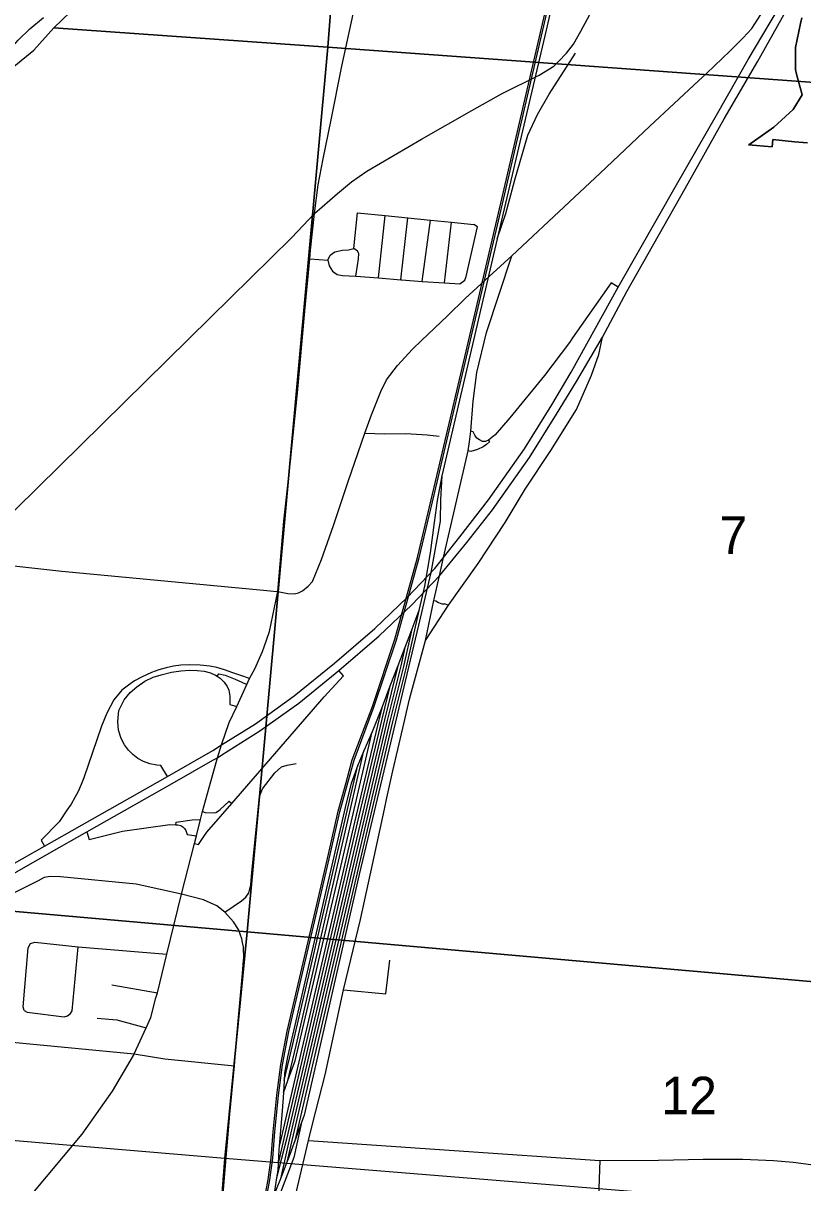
# Model space of a CAD drawing. Extents: x 0 to 34, y 0 to 22.
# Drawn here: x 4.57 to 5.442, y 14.854 to 16.149 of the extents above; entities that cross this region are included whole.
import ezdxf

# ---------------------------------------------------------------- set-up
doc = ezdxf.new("R2010")
doc.units = 0
for name, color, linetype in [('Default', 7, 'Continuous'), ('GM_X_City_Street', 7, 'Continuous'), ('GM_X_Interchange_Ramps', 7, 'Continuous'), ('GM_X_Interstate_Route', 7, 'Continuous'), ('GM_X_Major_River', 7, 'Continuous'), ('GM_X_Rail_Line', 7, 'Continuous'), ('GM_X_Section', 7, 'Continuous'), ('GM_X_Section_Text', 7, 'Continuous'), ('GM_X_State_Route', 7, 'Continuous'), ('SC_Shading3', 7, 'Continuous')]:
    doc.layers.add(name, color=color, linetype=linetype)

msp = doc.modelspace()

# ---------------------------------------------------------------- linework, layer by layer
at = {"layer": 'Default'}
for points in [[(3.9705, 14.1), (4.7349, 14.1), (4.7957, 14.8813), (4.1906, 14.9321), (4.0525, 14.6548), (3.9958, 14.4577), (3.9463, 14.3814), (3.9481, 14.3196)], [(4.7349, 14.1), (5.7681, 14.1), (5.8197, 14.7981), (4.7957, 14.8813)]]:
    msp.add_lwpolyline(points, close=True, dxfattribs=at)
at = {"layer": 'GM_X_City_Street'}
for p, q in [((4.9673, 15.8644), (4.975, 15.9342)), ((4.9923, 15.8625), (5.0002, 15.9317)), ((5.0161, 15.8606), (5.0253, 15.9291)), ((5.0411, 15.8591), (5.0491, 15.9267)), ((4.8906, 15.8858), (4.9107, 15.8843)), ((4.9754, 15.0651), (4.98, 15.1028)), ((4.6695, 15.075), (4.7203, 15.0661)), ((4.9281, 15.0695), (4.9754, 15.0651))]:
    msp.add_line(p, q, dxfattribs=at)
for points in [[(4.8397, 15.4527), (4.8456, 15.4697), (4.855, 15.5142), (4.8617, 15.5929), (4.869, 15.6599), (4.8767, 15.7363), (4.8851, 15.8274), (4.8906, 15.8858), (4.8915, 15.8956), (4.8959, 15.9365), (4.9, 15.9686), (4.9055, 15.9974), (4.9143, 16.0411), (4.9265, 16.101), (4.9418, 16.1711), (4.9536, 16.2272), (4.9641, 16.2778), (4.9703, 16.3128)], [(4.5149, 15.5535), (4.5216, 15.5642), (4.5305, 15.5745), (4.5624, 15.6068), (4.7794, 15.82), (4.87, 15.9094), (4.8959, 15.9365), (4.9216, 15.9589), (4.9372, 15.9717), (4.9543, 15.9837), (5.0154, 16.0193), (5.0715, 16.0516), (5.1047, 16.0699), (5.1468, 16.091), (5.1632, 16.1008), (5.1685, 16.1061), (5.1775, 16.1154), (5.1852, 16.1256), (5.1933, 16.1399), (5.2233, 16.1956), (5.23, 16.2068), (5.2368, 16.2142), (5.2425, 16.2183)], [(5.3343, 16.0932), (5.3599, 16.1177), (5.375, 16.1324), (5.3844, 16.1431), (5.3947, 16.1587), (5.4033, 16.173), (5.4082, 16.1836), (5.4117, 16.1912), (5.4129, 16.2047), (5.4122, 16.2135)], [(4.85, 15.5147), (4.855, 15.5142), (4.866, 15.5122), (4.8731, 15.5116), (4.8778, 15.5129), (4.8824, 15.5149), (4.8888, 15.5202), (4.8937, 15.5254), (4.9038, 15.5501), (4.917, 15.5879), (4.9336, 15.6372), (4.952, 15.6912), (4.9595, 15.7116), (4.9699, 15.7376), (4.9765, 15.7506), (4.9885, 15.7667), (5.0054, 15.785), (5.0153, 15.7946), (5.0444, 15.822), (5.0642, 15.8414), (5.0911, 15.866), (5.1163, 15.8891), (5.1809, 15.9495), (5.215, 15.9815), (5.2705, 16.0338), (5.3248, 16.0844), (5.3343, 16.0932)], [(4.9107, 15.8843), (4.9134, 15.8898), (4.9187, 15.8936), (4.9271, 15.8954), (4.9338, 15.8958), (4.9399, 15.8972), (4.9439, 15.9371)], [(4.9439, 15.9371), (4.975, 15.9342), (5.0002, 15.9317), (5.0253, 15.9291), (5.0491, 15.9267), (5.0739, 15.9242)], [(5.0582, 15.8579), (5.0637, 15.862), (5.0652, 15.8659), (5.0781, 15.9215), (5.0739, 15.9242)], [(4.9421, 15.8664), (4.9439, 15.8782), (4.9451, 15.8859), (4.9453, 15.8916), (4.9438, 15.8943), (4.9399, 15.8972)], [(5.0198, 15.4595), (5.0291, 15.5043), (5.0354, 15.5319), (5.0401, 15.5522), (5.0675, 15.6715), (5.0691, 15.6815), (5.0705, 15.6934), (5.0733, 15.7267), (5.0771, 15.759), (5.0879, 15.8035), (5.1163, 15.8891)], [(4.9107, 15.8843), (4.9123, 15.8779), (4.9161, 15.872), (4.9212, 15.8683), (4.9273, 15.8672), (4.9421, 15.8664), (4.9673, 15.8644), (4.9923, 15.8625), (4.9936, 15.8623), (5.0161, 15.8606), (5.0411, 15.8591), (5.0582, 15.8579)], [(4.952, 15.6912), (4.9745, 15.6905), (4.998, 15.6907), (5.0218, 15.6891), (5.0352, 15.6879)], [(4.5149, 15.5535), (4.525, 15.5488), (4.5328, 15.5458), (4.6135, 15.5372), (4.839, 15.5157), (4.85, 15.5147)], [(4.8234, 15.4172), (4.8293, 15.4281), (4.8379, 15.4473), (4.8397, 15.4527)], [(4.7684, 15.2597), (4.7707, 15.2685), (4.7801, 15.3021), (4.7873, 15.3287), (4.7921, 15.343), (4.8006, 15.3679), (4.809, 15.3859), (4.8202, 15.4103), (4.8234, 15.4172)], [(4.7958, 15.1563), (4.8142, 15.1689), (4.819, 15.1729), (4.8224, 15.1777), (4.8246, 15.1867), (4.8259, 15.2005), (4.8344, 15.2853), (4.8378, 15.2941), (4.8515, 15.3118), (4.8589, 15.3185), (4.8654, 15.3205), (4.8752, 15.3224)], [(4.7473, 15.1764), (4.7616, 15.2328), (4.7639, 15.2414), (4.7684, 15.2597)], [(4.7473, 15.1764), (4.6964, 15.1876), (4.612, 15.1957), (4.6004, 15.1961), (4.5936, 15.195), (4.5869, 15.1914), (4.5085, 15.1522), (4.4981, 15.1441), (4.4919, 15.1361), (4.4886, 15.1229), (4.4801, 15.0184)], [(4.7187, 15.0604), (4.7203, 15.0661), (4.7309, 15.1092), (4.7473, 15.1764)], [(4.7958, 15.1563), (4.7866, 15.1632), (4.7718, 15.17), (4.7473, 15.1764)], [(4.8155, 15.1224), (4.8147, 15.1264), (4.8108, 15.1369), (4.8055, 15.1456), (4.7958, 15.1563)], [(4.5714, 15.0466), (4.5704, 15.0506), (4.5759, 15.1163), (4.5786, 15.1211)], [(4.5786, 15.1211), (4.5835, 15.1228), (4.6317, 15.1176), (4.7309, 15.1092)], [(4.6233, 15.0432), (4.6249, 15.0462), (4.6317, 15.1176)], [(4.8165, 15.1025), (4.8167, 15.1045), (4.8165, 15.1175), (4.8155, 15.1224)], [(4.7877, 14.7751), (4.7915, 14.8137), (4.795, 14.8556), (4.8014, 14.9307), (4.8064, 14.9848), (4.8088, 15.0142), (4.8154, 15.0879), (4.8165, 15.1025)], [(4.6934, 14.9962), (4.6944, 14.9979), (4.7077, 15.0271), (4.7129, 15.0385), (4.7187, 15.0604)], [(4.5714, 15.0466), (4.5748, 15.0447), (4.6162, 15.0395), (4.6198, 15.0403), (4.6233, 15.0432)], [(4.653, 15.0379), (4.6749, 15.036), (4.7077, 15.0271)], [(4.3785, 15.0286), (4.4007, 15.026), (4.4801, 15.0184), (4.6944, 14.9979), (4.7286, 14.9924), (4.8064, 14.9848)], [(4.5036, 14.7192), (4.5157, 14.7466), (4.542, 14.7907), (4.5756, 14.8358), (4.6361, 14.9083), (4.67, 14.9564), (4.6934, 14.9962)], [(4.889, 14.9013), (5.2146, 14.8789), (5.2803, 14.8794), (5.3302, 14.8805), (5.3744, 14.8805), (5.4089, 14.8788), (5.4308, 14.8769), (5.4841, 14.8699), (5.5184, 14.8616), (5.5803, 14.8433), (5.6231, 14.829), (5.6609, 14.8201), (5.6846, 14.8159)], [(5.2146, 14.8789), (5.2126, 14.8172), (5.2077, 14.7541), (5.1981, 14.658), (5.1943, 14.628), (5.1877, 14.5576), (5.1889, 14.5431), (5.1938, 14.5246), (5.1999, 14.5119), (5.2062, 14.5004), (5.2164, 14.4886), (5.226, 14.4817), (5.2454, 14.4704), (5.345, 14.4199), (5.4323, 14.3694), (5.5063, 14.3244), (5.5711, 14.2911)]]:
    msp.add_lwpolyline(points, dxfattribs=at)
at = {"layer": 'GM_X_Interchange_Ramps'}
for points in [[(5.2353, 15.8542), (5.2273, 15.8589), (5.1843, 15.7976)], [(5.1843, 15.7976), (5.1807, 15.7925), (5.1529, 15.7555), (5.114, 15.7082), (5.0978, 15.6892), (5.0904, 15.6832)], [(5.0904, 15.6832), (5.0916, 15.6813), (5.0879, 15.6785), (5.0844, 15.676), (5.078, 15.673), (5.0706, 15.6708), (5.0675, 15.6715)], [(5.0904, 15.6832), (5.087, 15.6818), (5.0837, 15.682), (5.0802, 15.6835), (5.0773, 15.6854), (5.0749, 15.6889), (5.0732, 15.6927), (5.0705, 15.6934)], [(5.0291, 15.5043), (5.0313, 15.504), (5.0345, 15.5019), (5.0382, 15.5005), (5.0418, 15.5007), (5.0457, 15.4989)], [(4.8234, 15.4172), (4.8148, 15.42), (4.8045, 15.4235), (4.7952, 15.4269), (4.7866, 15.4293), (4.779, 15.4309), (4.7682, 15.4322), (4.7567, 15.4326), (4.7466, 15.432), (4.7384, 15.4309), (4.73, 15.4292), (4.722, 15.427), (4.7138, 15.424), (4.7025, 15.4188), (4.6948, 15.4144), (4.6881, 15.4099), (4.6807, 15.4041), (4.6716, 15.3935), (4.6637, 15.3784), (4.6578, 15.3639), (4.6381, 15.3064), (4.6352, 15.2989), (4.6317, 15.2911), (4.6282, 15.2844), (4.6238, 15.277), (4.6191, 15.27), (4.6104, 15.2572), (4.5905, 15.2365), (4.5943, 15.2301)], [(4.7317, 15.3079), (4.7243, 15.3201), (4.7197, 15.3202), (4.7119, 15.3218), (4.7048, 15.3245), (4.6984, 15.328), (4.6927, 15.3324), (4.6879, 15.3373), (4.6836, 15.3431), (4.6799, 15.3502), (4.677, 15.3594), (4.6759, 15.369), (4.6773, 15.3815), (4.6831, 15.3932), (4.69, 15.4017), (4.6972, 15.408), (4.7064, 15.414), (4.7157, 15.4186), (4.7244, 15.4214), (4.7361, 15.4242), (4.7463, 15.4258), (4.7565, 15.4266), (4.7646, 15.4262), (4.7725, 15.4253), (4.7797, 15.4234), (4.7854, 15.4209), (4.7871, 15.4198), (4.7905, 15.4176), (4.795, 15.4131), (4.7984, 15.4082), (4.8, 15.4042), (4.8012, 15.3976), (4.8013, 15.388), (4.809, 15.3859)], [(4.7616, 15.2328), (4.7664, 15.2317), (4.7722, 15.2408), (4.7755, 15.2454), (4.8033, 15.2775), (4.9067, 15.3968), (4.9284, 15.4202), (4.9231, 15.4262)], [(4.7871, 15.4198), (4.7891, 15.4225), (4.7961, 15.4207), (4.8073, 15.4166), (4.8148, 15.4131), (4.8202, 15.4103)], [(4.7707, 15.2685), (4.7738, 15.2676), (4.7829, 15.267), (4.7855, 15.2674), (4.7885, 15.2693), (4.7903, 15.271), (4.8004, 15.28), (4.8033, 15.2775)], [(4.6413, 15.2458), (4.6442, 15.2373), (4.6813, 15.2467), (4.7342, 15.2542), (4.7409, 15.2538), (4.743, 15.2536), (4.7464, 15.2529), (4.7486, 15.2514), (4.7505, 15.2497), (4.752, 15.2474), (4.7537, 15.243), (4.7639, 15.2414)], [(4.7409, 15.2538), (4.7411, 15.2566), (4.7591, 15.2593), (4.7684, 15.2597)]]:
    msp.add_lwpolyline(points, dxfattribs=at)
at = {"layer": 'GM_X_Interstate_Route'}
for points in [[(4.7921, 15.343), (4.8298, 15.3667), (4.8732, 15.3979), (4.9182, 15.4343), (4.9631, 15.4729), (4.9995, 15.5075), (5.0305, 15.54), (5.0401, 15.5522), (5.0584, 15.5755), (5.0902, 15.6165), (5.1305, 15.6735), (5.1609, 15.7227), (5.1825, 15.7591), (5.2353, 15.8542), (5.3003, 15.9684), (5.345, 16.0461), (5.3805, 16.1084), (5.4224, 16.1794), (5.4322, 16.1982)], [(5.2177, 15.7982), (5.245, 15.8495), (5.3099, 15.9645), (5.3538, 16.0423), (5.3911, 16.1066), (5.4309, 16.1772), (5.4366, 16.1874)], [(4.7922, 15.3318), (4.8348, 15.3586), (4.8782, 15.3898), (4.9231, 15.4262), (4.9681, 15.4648), (5.0045, 15.4994), (5.0354, 15.5319), (5.0661, 15.569), (5.0949, 15.6056), (5.1363, 15.6639), (5.1664, 15.7122), (5.1887, 15.749), (5.2177, 15.7982)], [(4.3958, 15.0979), (4.3965, 15.0986), (4.411, 15.1122), (4.4246, 15.1249), (4.4406, 15.1364), (4.4557, 15.1489), (4.4695, 15.1575), (4.4939, 15.1734), (4.5199, 15.1877), (4.544, 15.2017), (4.5943, 15.2301), (4.6364, 15.2539), (4.7317, 15.3079), (4.7824, 15.3368), (4.7921, 15.343)], [(4.3383, 15.0004), (4.3568, 15.0308), (4.3814, 15.0645), (4.4051, 15.0915), (4.4356, 15.12), (4.4626, 15.1408), (4.4941, 15.1619), (4.5273, 15.181), (4.5992, 15.222), (4.6413, 15.2458), (4.7367, 15.2999), (4.7823, 15.3258)], [(4.7823, 15.3258), (4.7873, 15.3287), (4.7922, 15.3318)]]:
    msp.add_lwpolyline(points, dxfattribs=at)
at = {"layer": 'GM_X_Major_River'}
msp.add_lwpolyline([(4.3831, 15.9009), (4.389, 15.9129), (4.3945, 15.9231), (4.4001, 15.9359), (4.4049, 15.9506), (4.4145, 15.974), (4.42, 15.9838), (4.4286, 15.9981), (4.4387, 16.0097), (4.4503, 16.0231), (4.4612, 16.0351), (4.4739, 16.047), (4.4843, 16.0548), (4.4966, 16.0633), (4.5063, 16.0699), (4.5171, 16.0811), (4.5302, 16.093), (4.5434, 16.1069), (4.5542, 16.1181), (4.5647, 16.13), (4.5779, 16.1427), (4.5929, 16.1553)], dxfattribs=at)
at = {"layer": 'GM_X_Rail_Line'}
for p, q in [((5.0124, 15.4931), (5.0046, 15.4724)), ((4.989, 15.4314), (4.9802, 15.4085)), ((4.9802, 15.4085), (4.9713, 15.3856)), ((4.9713, 15.3856), (4.9604, 15.3576)), ((4.9604, 15.3576), (4.9511, 15.3364)), ((4.862, 14.9682), (4.8611, 14.9545)), ((4.8611, 14.9545), (4.866, 14.9681)), ((4.8649, 14.8771), (4.8577, 14.8584)), ((4.8535, 14.8594), (4.8501, 14.8374))]:
    msp.add_line(p, q, dxfattribs=at)
for points in [[(4.839, 14.8294), (4.8441, 14.8577), (4.8473, 14.8818), (4.8498, 14.9111), (4.8536, 14.9518), (4.8581, 14.9862), (4.8654, 15.0235), (4.901, 15.1758), (4.9115, 15.221), (4.9223, 15.2689), (4.9311, 15.301), (4.9381, 15.3264), (4.9605, 15.3858), (4.9858, 15.4611), (5.0111, 15.5524), (5.0295, 15.6307), (5.0403, 15.6765), (5.0637, 15.7765), (5.104, 15.9478), (5.2062, 16.3872)], [(4.8409, 14.829), (4.846, 14.8574), (4.8492, 14.8816), (4.8517, 14.911), (4.8555, 14.9516), (4.86, 14.9859), (4.8673, 15.0231), (4.9029, 15.1754), (4.9134, 15.2206), (4.9242, 15.2684), (4.933, 15.3005), (4.94, 15.3258), (4.9623, 15.3852), (4.9876, 15.4605), (5.013, 15.5519), (5.0313, 15.6302), (5.0422, 15.6761), (5.0656, 15.7761), (5.1058, 15.9473), (5.2081, 16.3868)], [(5.1737, 16.2391), (5.1682, 16.2002), (5.1547, 16.1411), (5.1078, 15.9417), (5.038, 15.6433)], [(5.1, 15.9083), (5.1095, 15.9365), (5.1199, 15.9739), (5.1341, 16.0238), (5.1452, 16.0469), (5.1581, 16.0697), (5.1875, 16.1155)], [(5.038, 15.6433), (5.0367, 15.617), (5.0364, 15.5929), (5.026, 15.5354), (5.0141, 15.4844), (4.9459, 15.1982), (4.8842, 14.9294), (4.8737, 14.9007)], [(5.038, 15.6433), (5.0331, 15.616), (5.0295, 15.5914), (5.0252, 15.5575), (5.0186, 15.5204), (5.0124, 15.4931)], [(5.0124, 15.4931), (4.9982, 15.4299), (4.9831, 15.3688), (4.9558, 15.253), (4.8737, 14.9007)], [(5.0046, 15.4724), (4.9952, 15.4306), (4.9801, 15.3695), (4.9528, 15.2537), (4.8706, 14.9014), (4.8649, 14.8771)], [(5.0046, 15.4724), (5.0012, 15.4635), (4.9968, 15.4517)], [(4.9968, 15.4517), (4.9922, 15.4314), (4.9771, 15.3702), (4.9498, 15.2544), (4.8676, 14.9021), (4.8577, 14.8584)], [(4.9968, 15.4517), (4.992, 15.4391), (4.989, 15.4314)], [(4.989, 15.4314), (4.9741, 15.371), (4.9468, 15.2552), (4.8646, 14.9028), (4.8535, 14.8594)], [(4.9802, 15.4085), (4.971, 15.3717), (4.9437, 15.2559), (4.8615, 14.9035), (4.8552, 14.8756)], [(4.9713, 15.3856), (4.968, 15.3724), (4.9407, 15.2566), (4.8585, 14.9042), (4.8562, 14.895)], [(4.866, 14.9681), (4.869, 14.9765), (4.8743, 14.9903), (4.9368, 15.2563), (4.9604, 15.3576)], [(4.866, 14.9681), (4.8754, 15.0074), (4.9511, 15.3364)], [(4.9511, 15.3364), (4.946, 15.3247), (4.9443, 15.3202)], [(4.862, 14.9682), (4.8717, 15.0087), (4.9443, 15.3202)], [(4.9443, 15.3202), (4.9368, 15.3), (4.9312, 15.278), (4.8657, 14.9946), (4.8624, 14.9765), (4.862, 14.9682)], [(4.8611, 14.9545), (4.8598, 14.9344), (4.8562, 14.895)], [(4.8813, 14.9215), (4.8726, 14.8821), (4.8628, 14.8558), (4.85, 14.8226), (4.8414, 14.7911), (4.8378, 14.7723), (4.8371, 14.7555), (4.8437, 14.7289), (4.8542, 14.7079), (4.8667, 14.6901), (4.8832, 14.676), (4.9032, 14.6641), (4.9272, 14.6562), (4.9509, 14.6562), (4.968, 14.6567)], [(4.8562, 14.895), (4.8559, 14.8913), (4.8552, 14.8756)], [(4.8737, 14.9007), (4.867, 14.8825), (4.8649, 14.8771)], [(4.8552, 14.8756), (4.8549, 14.868), (4.8535, 14.8594)], [(4.8577, 14.8584), (4.853, 14.8464), (4.8501, 14.8374)]]:
    msp.add_lwpolyline(points, dxfattribs=at)
at = {"layer": 'GM_X_Section'}
for points in [[(4.6046, 16.1438), (4.7052, 16.2404), (4.8924, 16.385), (4.9329, 16.4073), (4.9109, 16.1221)], [(4.9329, 16.4073), (4.9747, 16.391), (5.0349, 16.3524), (5.1555, 16.2978), (5.2124, 16.265), (5.3126, 16.2343), (5.437, 16.2217), (5.569, 16.217), (5.709, 16.1875), (5.8473, 16.1527), (5.9234, 16.1293), (5.9113, 16.0496), (4.9109, 16.1221)], [(4.6046, 16.1438), (4.9109, 16.1221), (4.8205, 15.1342), (4.2945, 15.1804), (4.324, 15.239), (4.3447, 15.3749), (4.3532, 15.5236), (4.3623, 15.7454), (4.3778, 15.8443), (4.4109, 15.9156), (4.4783, 16.0344), (4.5821, 16.1188)], [(4.9109, 16.1221), (5.9113, 16.0496), (5.8133, 15.0467), (4.8205, 15.1342)], [(4.2945, 15.1804), (4.8205, 15.1342), (4.7957, 14.8813), (4.1906, 14.9321), (4.222, 15.0068), (4.26, 15.0762), (4.2906, 15.1529)], [(4.8205, 15.1342), (5.8133, 15.0467), (5.8372, 15.0451), (5.8197, 14.7981), (4.7957, 14.8813)]]:
    msp.add_lwpolyline(points, close=True, dxfattribs=at)
at = {"layer": 'GM_X_State_Route'}
msp.add_line((4.889, 14.9013), (4.894, 14.9209), dxfattribs=at)
for points in [[(5.4405, 16.1551), (5.4391, 16.1486), (5.4333, 16.1219), (5.4332, 16.0973), (5.4346, 16.0919), (5.4407, 16.0689), (5.4407, 16.0688), (5.4308, 16.0526), (5.4093, 16.033), (5.3811, 16.0131), (5.3809, 16.013), (5.4074, 16.0107), (5.4081, 16.0191), (5.4324, 16.0166), (5.4468, 16.0152)], [(5.0198, 15.4595), (5.0457, 15.4989), (5.0786, 15.5454), (5.1089, 15.5914), (5.1313, 15.6287), (5.1601, 15.6716), (5.1887, 15.7176), (5.2054, 15.7559), (5.2135, 15.7791), (5.2177, 15.7982)], [(4.9767, 15.284), (4.9833, 15.314), (4.9944, 15.3618), (5.0021, 15.3942), (5.0198, 15.4595)], [(4.894, 14.9209), (4.9077, 14.9747), (4.9281, 15.0695), (4.9471, 15.148), (4.9605, 15.2095), (4.9739, 15.2714), (4.9767, 15.284)], [(4.8551, 14.7344), (4.8562, 14.7504), (4.8615, 14.7842), (4.889, 14.9013)]]:
    msp.add_lwpolyline(points, dxfattribs=at)
at = {"layer": 'SC_Shading3'}
msp.add_lwpolyline([(5.4468, 16.0152), (5.4324, 16.0166), (5.4081, 16.0191), (5.4074, 16.0107), (5.3809, 16.013), (5.3811, 16.0131), (5.4093, 16.033), (5.4308, 16.0526), (5.4407, 16.0688), (5.4407, 16.0689), (5.4346, 16.0919), (5.4332, 16.0973), (5.4333, 16.1218), (5.4333, 16.1219), (5.4391, 16.1486), (5.4405, 16.1551)], dxfattribs=at)

# ---------------------------------------------------------------- texts
at = {"layer": 'GM_X_Section_Text'}
for s, height, p in [('7', 0.0419, (5.3483, 15.5563)), ('12', 0.04186, (5.2833, 14.9306))]:
    msp.add_text(s, height=height, rotation=0, dxfattribs=at).set_placement(p)

doc.saveas('drawing.dxf')
